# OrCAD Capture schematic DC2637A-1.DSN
size B; title: 20V, 2A, PARALLELED ULTRALOW NOISE,; rev: 1; note: DC2637A
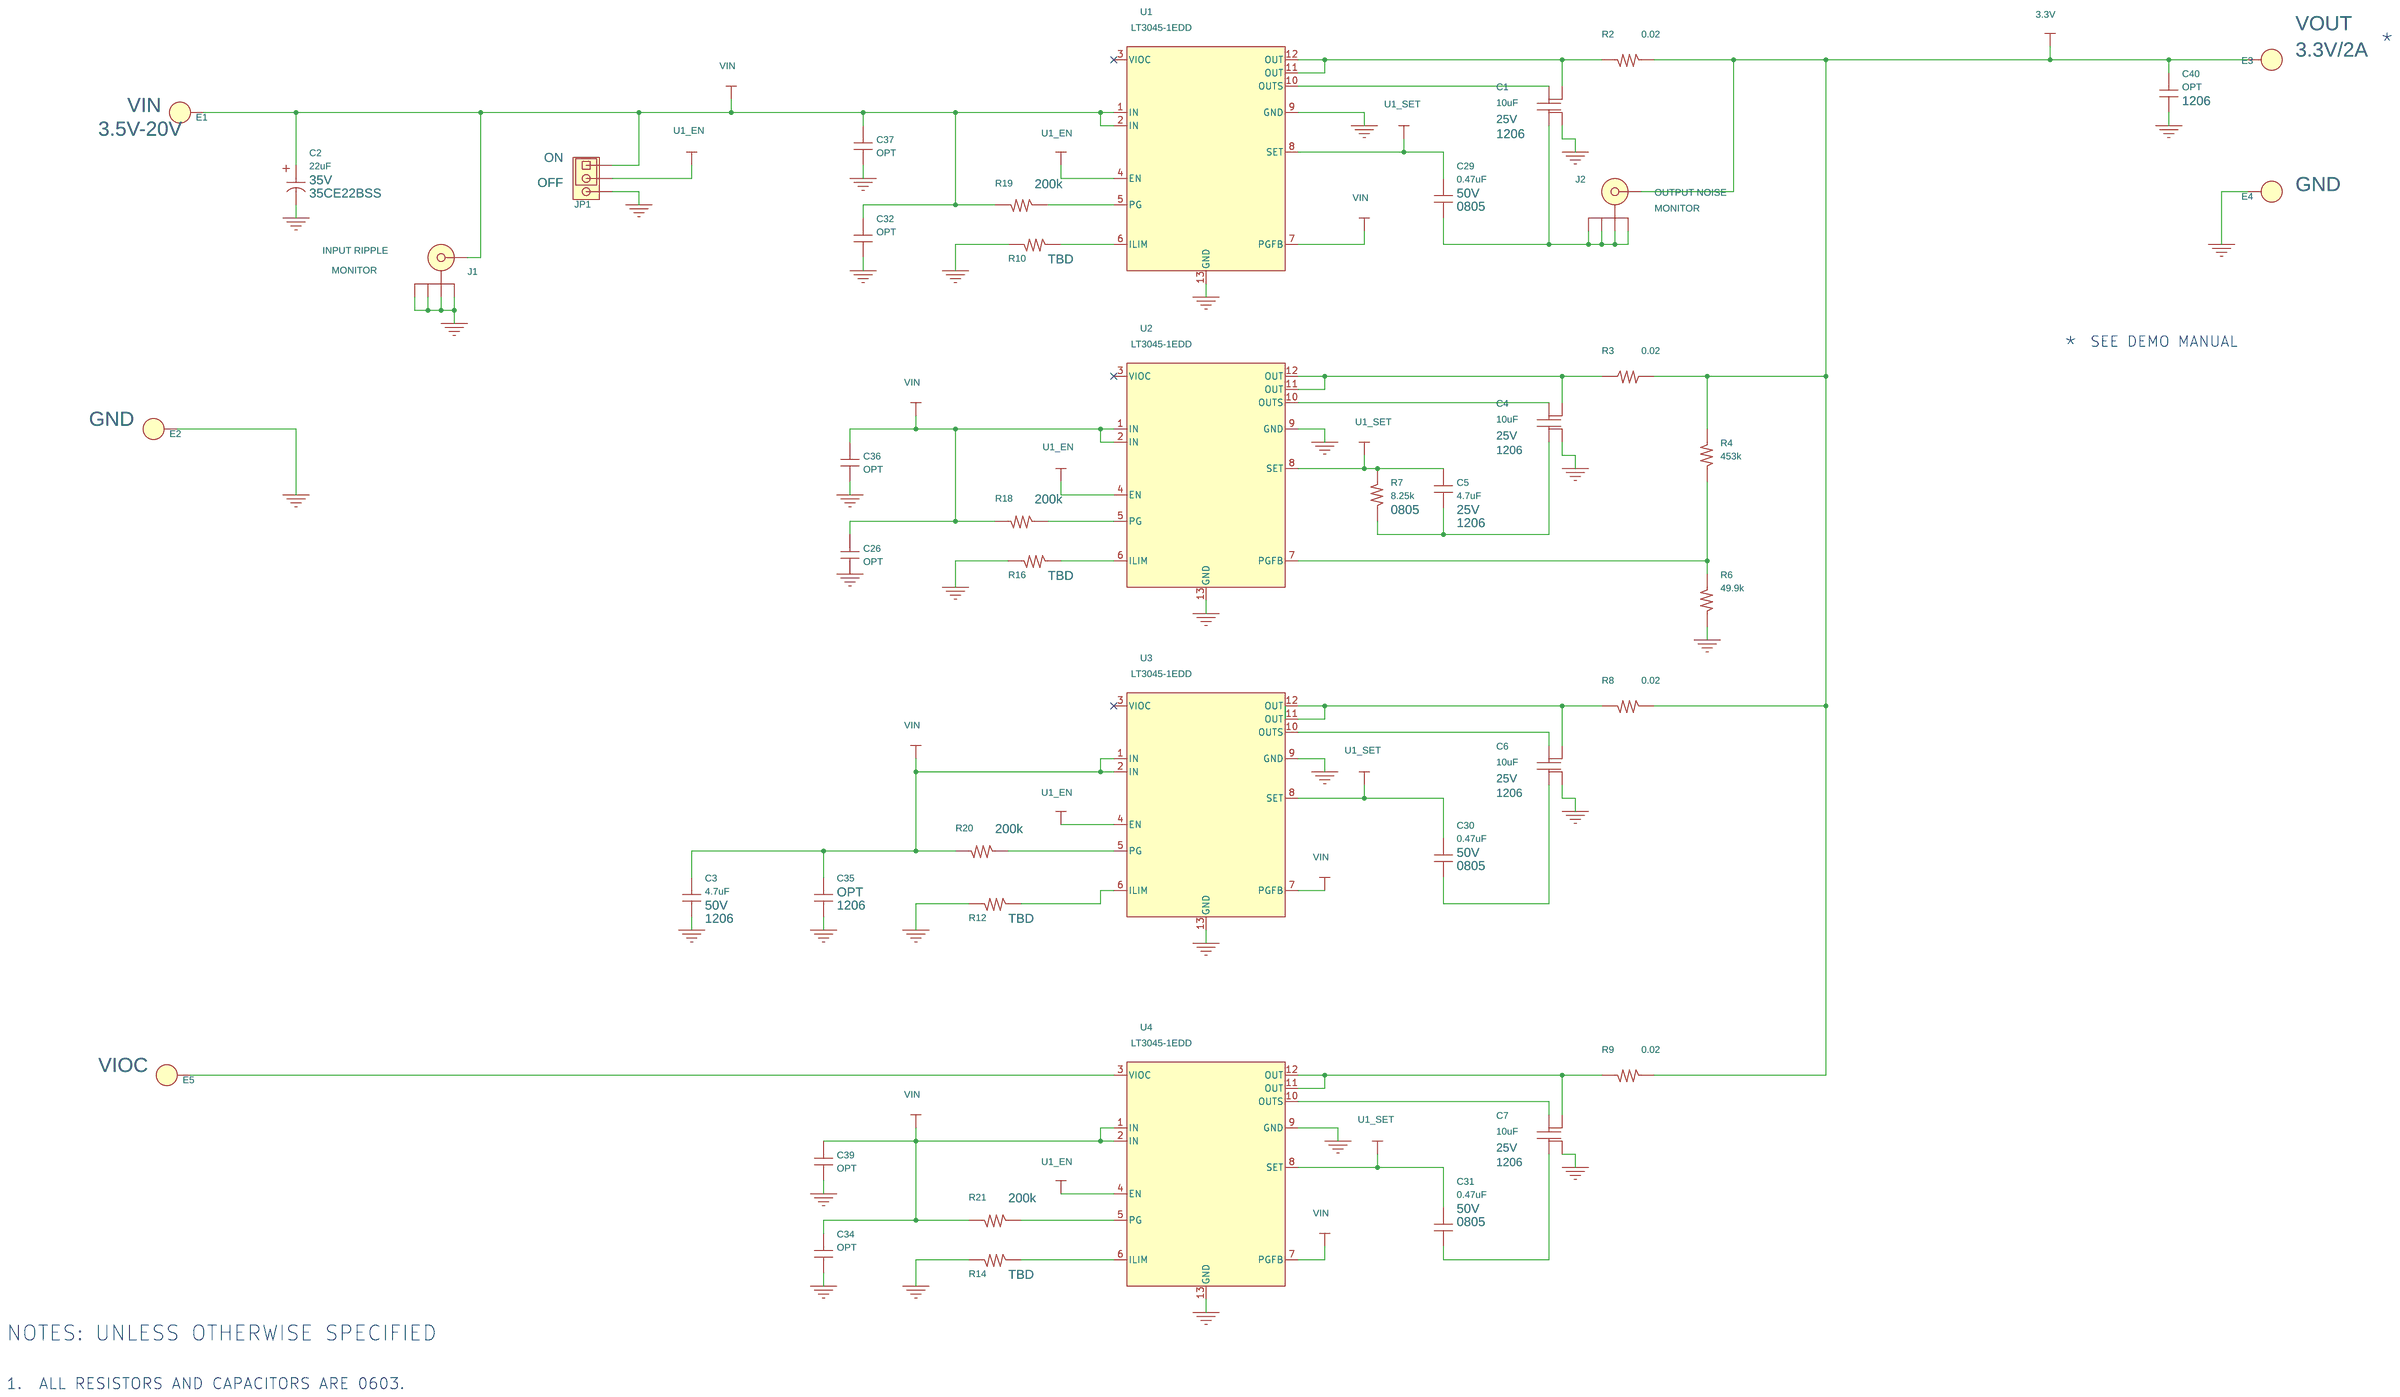
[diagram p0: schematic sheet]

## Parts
C1  10uF  [1206-SP]
C2  22uF  [CAP-CE-5X5.4]
C3  4.7uF  [1206]
C4  10uF  [1206-SP]
C5  4.7uF  [1206]
C6  10uF  [1206-SP]
C7  10uF  [1206-SP]
C26  OPT  [0603]
C29  0.47uF  [0805]
C30  0.47uF  [0805]
C31  0.47uF  [0805]
C32  OPT  [0603]
C34  OPT  [0603]
C35  4.7uF  [1206]
C36  OPT  [0603]
C37  OPT  [0603]
C39  OPT  [0603]
C40  OPT  [1206]
E1  VIN  [MM/2501]
E2  GND  [MM/2501]
E3  3.3V/2A  [MM/2501]
E4  GND  [MM/2501]
E5  VIOC  [MM/2501]
J1  MONITOR  [BNC5]
J2  MONITOR  [BNC5]
JP1  HD1X3-079  [JP3X1/079]
R2  0.02  [0603]
R3  0.02  [0603]
R4  453k  [0603]
R6  49.9k  [0603]
R7  8.25k  [0805]
R8  0.02  [0603]
R9  0.02  [0603]
R10  TBD  [0603]
R12  TBD  [0603]
R14  TBD  [0603]
R16  TBD  [0603]
R18  200k  [0603]
R19  200k  [0603]
R20  200k  [0603]
R21  200k  [0603]
U1  LT3045-1EDD  [DFN-12(3X3)]
U2  LT3045-1EDD  [DFN-12(3X3)]
U3  LT3045-1EDD  [DFN-12(3X3)]
U4  LT3045-1EDD  [DFN-12(3X3)]

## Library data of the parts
C1 C4 C7 = CAP_NP_1: 1ST PART FIELD: 25V; 2nd Part Field: 1206
C2 = CAP: 1st Part Field: 35CE22BSS; Descriptions: CAP., ALUM, 35V, 27uF; OPT: OPT; Package Type: 7343; VOLTAGE: 35V
C3 C29-C31 = CAP-NP: 5th Part Field: 12065C104KATM; 7th Part Field: CAP.,; VOLTAGE: 50V
C5 = CAP-NP: 5th Part Field: 12065C104KATM; 7th Part Field: CAP.,; VOLTAGE: 25V
C6 = CAP_NP_1: 1ST PART FIELD: 25V; 2nd Part Field: 1206; Voltage: 25V
C26 C32 C34 C36 C37 C39 C40 = CAP-NP: 5th Part Field: 12065C104KATM; 7th Part Field: CAP.,
C35 = CAP-NP: 5th Part Field: 12065C104KATM; 7th Part Field: CAP.,; VOLTAGE: OPT
E1 E2 = MillMax-2501_0: 1ST PART FIELD: *; Value1: 3.5V-20V
E3 = MillMax-2501_0: 1ST PART FIELD: *; Value1: VOUT
E4 E5 = MillMax-2501_0: 1ST PART FIELD: *; Value1: 3.8V-20V
J1 = BNC_0: 1ST PART FIELD: INPUT RIPPLE
J2 = BNC_0: 1ST PART FIELD: OUTPUT NOISE
JP1 = HD1X3: 1st Part Field: 3.3V; 2nd Part Field: ON; 3rd Part Field: OFF
R2 R3 R8 R9 = R: Descriptions: RES., 0.02OHM, 0603
R4 = R: Descriptions: RES., 453K, 0603
R6 = R: Descriptions: RES., 49.9K, 0603
R7 = R
R10 R14 R16 = R: Descriptions: RES., TBD, 0603
R12 = R: Descriptions: RES.,TBD, 0603
R18-R21 = R: Descriptions: RES., 200k, 0603
U1 U3 U4 = LT3042EDD_28
U2 = LT3042EDD_27

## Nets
3.3V: C40.2 E3.1 J2.1 R2.1 R3.2 R4.2 R8.1 R9.1
GND: C1.1 C2.2 C3.1 C4.1 C6.1 C7.1 C26.1 C32.1 C34.1 C35.1 C36.1 C37.1 C39.1 C40.1 E2.1 E4.1 J1.2 J1.3 J1.4 J1.5 JP1.3 R6.1 R10.2 R12.2 R14.2 R16.2 U1.9(GND) U1.13(GND) U2.9(GND) U2.13(GND) U3.9(GND) U3.13(GND) U4.9(GND) U4.13(GND)
VIN: C2.1 C3.2 C26.2 C32.2 C34.2 C35.2 C36.2 C37.2 C39.2 E1.1 J1.1 JP1.1 R18.2 R19.2 R20.2 R21.2 U1.1(IN) U1.2(IN) U1.7(PGFB) U2.1(IN) U2.2(IN) U3.1(IN) U3.2(IN) U3.7(PGFB) U4.1(IN) U4.2(IN) U4.7(PGFB)
U1_EN: JP1.2 U1.4(EN) U2.4(EN) U3.4(EN) U4.4(EN)
U1_SET: C5.2 C29.2 C30.2 C31.2 R7.2 U1.8(SET) U2.8(SET) U3.8(SET) U4.8(SET)
N17829005: C4.2 R3.1 U2.11(OUT) U2.12(OUT)
N17932856: R4.1 R6.2 U2.7(PGFB)
N18139571: C4.4 U2.10(OUTS)
N18145505: C1.2 R2.2 U1.11(OUT) U1.12(OUT)
N18145522: C1.4 U1.10(OUTS)
N18146350: R10.1 U1.6(ILIM)
N18148201: C6.4 U3.10(OUTS)
N18148235: R12.1 U3.6(ILIM)
N18149975: C7.2 R9.2 U4.11(OUT) U4.12(OUT)
N18149999: C7.4 U4.10(OUTS)
N18150033: R14.1 U4.6(ILIM)
N18156181: R16.1 U2.6(ILIM)
N18157359: E5.1 U4.3(VIOC)
N18160167: R19.1 U1.5(PG)
N18160227: R20.1 U3.5(PG)
N18160289: R21.1 U4.5(PG)
N18161463: R18.1 U2.5(PG)
N18173126: C4.3 C5.1 R7.1
N18174625: C7.3 C31.1
N18175437: C6.3 C30.1
N18181493: C1.3 C29.1 J2.2 J2.3 J2.4 J2.5
N18190569: C6.2 R8.2 U3.11(OUT) U3.12(OUT)

Not connected (* = marked no-connect by the designer): U1 3(VIOC)*; U2 3(VIOC)*; U3 3(VIOC)*

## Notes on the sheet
- *
- *
- SEE DEMO MANUAL
- NOTES: UNLESS OTHERWISE SPECIFIED
- 1.  ALL RESISTORS AND CAPACITORS ARE 0603.
